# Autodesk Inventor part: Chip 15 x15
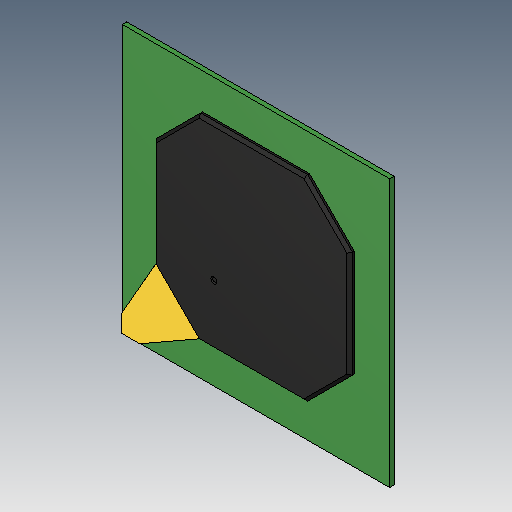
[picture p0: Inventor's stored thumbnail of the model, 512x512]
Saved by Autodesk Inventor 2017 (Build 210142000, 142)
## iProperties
Created: 2005-12
Part Number: Chip 15 x15
Material: Generic
Document SubType Name: Modeling
Designer: DanielSeverino
Density: 1 g/cm^3
Appearance: Default
Author: DanielSeverino
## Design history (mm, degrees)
feature "Solid1"
body "Solid2"
